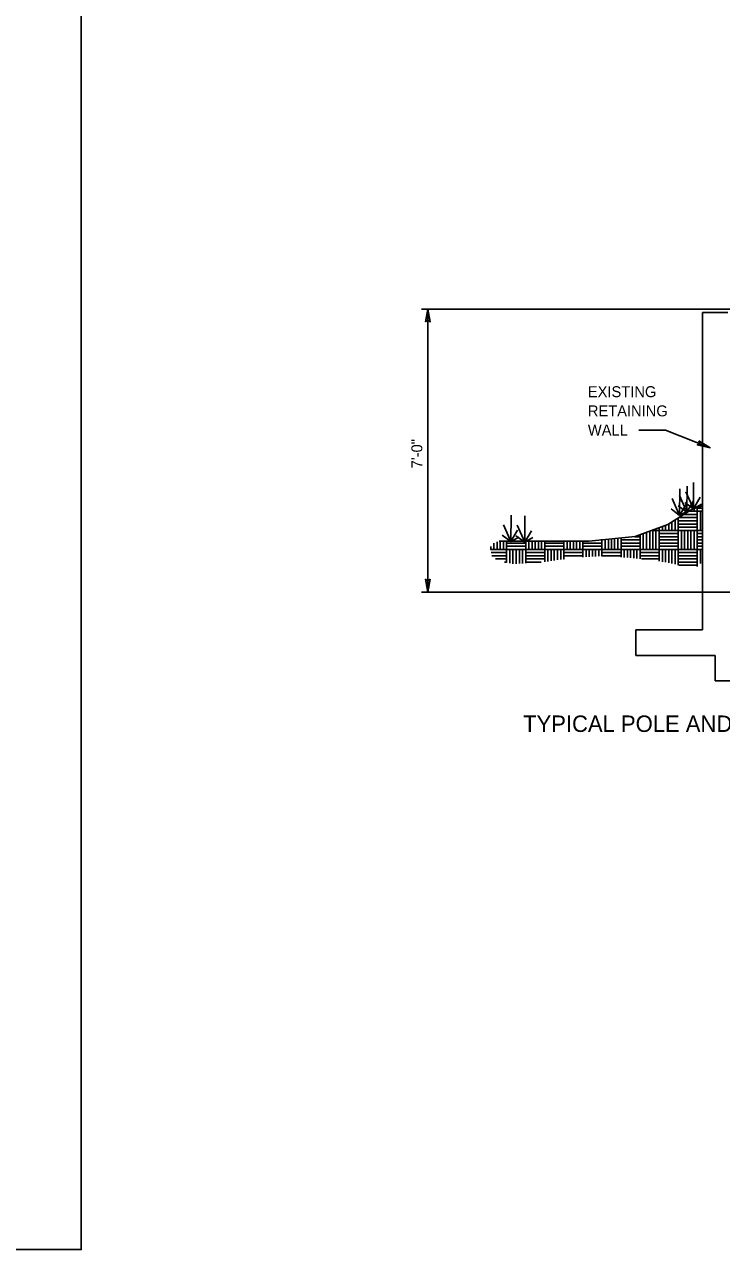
# Model space of a CAD drawing. Extents: x 99836 to 115004, y 99786 to 102182.
# Drawn here: x 113314 to 114076, y 99886 to 101226 of the extents above; entities that cross this region are included whole.
import ezdxf

# ---------------------------------------------------------------- set-up
doc = ezdxf.new("R2010")
doc.units = 0
doc.layers.add('Border Organizer Shape', color=7, linetype='Continuous')
doc.layers.add('Default', color=7, linetype='Continuous')

msp = doc.modelspace()

# ---------------------------------------------------------------- linework, layer by layer
at = {"layer": 'Border Organizer Shape'}
for p, q in [((114104.3, 100915.1), (113748, 100915.1)), ((113755.1, 100605.4), (113755.1, 100915.1)), ((114055.4, 100564), (114055.4, 100911.5)), ((114083.2, 100911.5), (114055.4, 100911.5)), ((113985.7, 100782.7), (114014.9, 100782.7)), ((114014.9, 100782.7), (114063.7, 100763.4)), ((114030.5, 100689.4), (114030.8, 100718.3)), ((114045.6, 100696.6), (114037.4, 100715)), ((114038.4, 100692.7), (114038.6, 100721.5)), ((114045.6, 100696.6), (114045.8, 100725.4)), ((114030.5, 100689.4), (114022.4, 100707.9)), ((114038.4, 100692.7), (114030.3, 100711.1)), ((114030.5, 100689.4), (114037.9, 100702)), ((114045.6, 100696.6), (114036.1, 100703.6)), ((114038.4, 100692.7), (114045.7, 100705.3)), ((114045.6, 100696.6), (114052.9, 100709.2)), ((114045.6, 100696.6), (114054.5, 100701.6)), ((113846, 100660.7), (113846.2, 100689.5)), ((113861, 100660.1), (113861.2, 100688.9)), ((114017.4, 100679.4), (114044, 100696)), ((114030.5, 100689.4), (114021.1, 100696.4)), ((114038.4, 100692.7), (114029, 100699.7)), ((114030.5, 100689.4), (114039.5, 100694.4)), ((114035, 100690.4), (114049.8, 100690.4)), ((114038.4, 100692.7), (114047.3, 100697.7)), ((114040.5, 100693.8), (114049.8, 100693.8)), ((114042.8, 100693.8), (114042.8, 100695.3)), ((114044, 100696), (114055.4, 100699.8)), ((114046.3, 100693.8), (114046.3, 100696.8)), ((114049.8, 100693.8), (114049.8, 100697.9)), ((114049.8, 100697.3), (114055.4, 100697.3)), ((114049.8, 100673), (114049.8, 100693.8)), ((114049.8, 100693.8), (114055.4, 100693.8)), ((114053.3, 100673), (114053.3, 100693.8)), ((113846, 100660.7), (113837.8, 100679.1)), ((113861, 100660.1), (113852.9, 100678.5)), ((113981.9, 100666.1), (114017.4, 100679.4)), ((114008.1, 100673), (114008.1, 100675.9)), ((114011.6, 100673), (114011.6, 100677.2)), ((114015, 100673), (114015, 100678.5)), ((114018.5, 100673), (114018.5, 100680.1)), ((114022, 100673), (114022, 100682.3)), ((114025.5, 100673), (114025.5, 100684.4)), ((114028.9, 100673), (114028.9, 100686.6)), ((114028.9, 100683.4), (114049.8, 100683.4)), ((114028.9, 100679.9), (114049.8, 100679.9)), ((114028.9, 100676.5), (114049.8, 100676.5)), ((114029.4, 100686.9), (114049.8, 100686.9)), ((113830.9, 100652.1), (113830.9, 100660.5)), ((113833, 100661.3), (113931, 100661.3)), ((113834.3, 100652.1), (113834.3, 100661.3)), ((113846, 100660.7), (113836.5, 100667.7)), ((113837.8, 100652.1), (113837.8, 100661.3)), ((113841.3, 100652.1), (113841.3, 100661.3)), ((113846, 100660.7), (113853.3, 100673.3)), ((113846, 100660.7), (113854.9, 100665.7)), ((113861, 100660.1), (113851.5, 100667)), ((113861, 100660.1), (113868.3, 100672.6)), ((113861, 100660.1), (113869.9, 100665)), ((113862.1, 100652.1), (113862.1, 100661.3)), ((113865.6, 100652.1), (113865.6, 100661.3)), ((113869.1, 100652.1), (113869.1, 100661.3)), ((113872.6, 100652.1), (113872.6, 100661.3)), ((113876, 100652.1), (113876, 100661.3)), ((113879.5, 100652.1), (113879.5, 100661.3)), ((113883, 100652.1), (113883, 100661.3)), ((113903.8, 100652.1), (113903.8, 100661.3)), ((113907.3, 100652.1), (113907.3, 100661.3)), ((113910.8, 100652.1), (113910.8, 100661.3)), ((113914.3, 100652.1), (113914.3, 100661.3)), ((113917.7, 100652.1), (113917.7, 100661.3)), ((113921.2, 100652.1), (113921.2, 100661.3)), ((113924.7, 100652.1), (113924.7, 100661.3)), ((113931, 100661.3), (113981.9, 100666.1)), ((113944.4, 100662.6), (113945.5, 100662.6)), ((113945.5, 100652.1), (113945.5, 100662.7)), ((113949, 100652.1), (113949, 100663)), ((113952.5, 100652.1), (113952.5, 100663.3)), ((113956, 100652.1), (113956, 100663.7)), ((113959.4, 100652.1), (113959.4, 100664)), ((113962.9, 100652.1), (113962.9, 100664.3)), ((113966.4, 100652.1), (113966.4, 100664.6)), ((113966.4, 100662.6), (113987.2, 100662.6)), ((113981.6, 100666), (113987.2, 100666)), ((113987.2, 100652.1), (113987.2, 100668.1)), ((113990.7, 100652.1), (113990.7, 100669.4)), ((113994.2, 100652.1), (113994.2, 100670.7)), ((113997.7, 100652.1), (113997.7, 100672)), ((114000.4, 100673), (114008.1, 100673)), ((114001.1, 100652.1), (114001.1, 100673)), ((114004.6, 100652.1), (114004.6, 100673)), ((114008.1, 100652.1), (114008.1, 100673)), ((114008.1, 100673), (114028.9, 100673)), ((114008.1, 100669.5), (114028.9, 100669.5)), ((114008.1, 100666), (114028.9, 100666)), ((114008.1, 100662.6), (114028.9, 100662.6)), ((114028.9, 100652.1), (114028.9, 100673)), ((114028.9, 100673), (114049.8, 100673)), ((114032.4, 100652.1), (114032.4, 100673)), ((114035.9, 100652.1), (114035.9, 100673)), ((114039.4, 100652.1), (114039.4, 100673)), ((114042.8, 100652.1), (114042.8, 100673)), ((114046.3, 100652.1), (114046.3, 100673)), ((114049.8, 100652.1), (114049.8, 100673)), ((114049.8, 100673), (114055.5, 100673)), ((114049.8, 100669.5), (114055.5, 100669.5)), ((114049.8, 100666), (114055.5, 100666)), ((114049.8, 100662.6), (114055.5, 100662.6)), ((113823.8, 100652.1), (113841.3, 100652.1)), ((113823.9, 100652.1), (113823.9, 100655.3)), ((113824.4, 100648.7), (113841.3, 100648.7)), ((113827.4, 100652.1), (113827.4, 100659.1)), ((113841.3, 100659.1), (113862.1, 100659.1)), ((113841.3, 100655.6), (113862.1, 100655.6)), ((113841.3, 100637.8), (113841.3, 100652.1)), ((113841.3, 100652.1), (113862.1, 100652.1)), ((113844.8, 100637), (113844.8, 100652.1)), ((113848.2, 100636.2), (113848.2, 100652.1)), ((113851.7, 100636.4), (113851.7, 100652.1)), ((113855.2, 100636.6), (113855.2, 100652.1)), ((113858.7, 100636.8), (113858.7, 100652.1)), ((113862.1, 100637.1), (113862.1, 100652.1)), ((113862.1, 100652.1), (113883, 100652.1)), ((113862.1, 100648.7), (113883, 100648.7)), ((113883, 100659.1), (113903.8, 100659.1)), ((113883, 100655.6), (113903.8, 100655.6)), ((113883, 100638.5), (113883, 100652.1)), ((113883, 100652.1), (113903.8, 100652.1)), ((113886.5, 100638.9), (113886.5, 100652.1)), ((113889.9, 100639.5), (113889.9, 100652.1)), ((113893.4, 100640), (113893.4, 100652.1)), ((113896.9, 100640.6), (113896.9, 100652.1)), ((113900.4, 100641.1), (113900.4, 100652.1)), ((113903.8, 100641.6), (113903.8, 100652.1)), ((113903.8, 100652.1), (113924.7, 100652.1)), ((113903.8, 100648.7), (113924.7, 100648.7)), ((113924.7, 100659.1), (113945.5, 100659.1)), ((113924.7, 100655.6), (113945.5, 100655.6)), ((113924.7, 100643.7), (113924.7, 100652.1)), ((113924.7, 100652.1), (113945.5, 100652.1)), ((113928.2, 100643.9), (113928.2, 100652.1)), ((113931.6, 100644.1), (113931.6, 100652.1)), ((113935.1, 100644.3), (113935.1, 100652.1)), ((113938.6, 100644.4), (113938.6, 100652.1)), ((113942.1, 100644.6), (113942.1, 100652.1)), ((113945.5, 100644.8), (113945.5, 100652.1)), ((113945.5, 100652.1), (113966.4, 100652.1)), ((113945.5, 100648.7), (113966.4, 100648.7)), ((113966.4, 100659.1), (113987.2, 100659.1)), ((113966.4, 100655.6), (113987.2, 100655.6)), ((113966.4, 100643.6), (113966.4, 100652.1)), ((113966.4, 100652.1), (113987.2, 100652.1)), ((113969.9, 100643.4), (113969.9, 100652.1)), ((113973.3, 100643.1), (113973.3, 100652.1)), ((113976.8, 100642.9), (113976.8, 100652.1)), ((113980.3, 100642.6), (113980.3, 100652.1)), ((113983.8, 100642.2), (113983.8, 100652.1)), ((113987.2, 100641.9), (113987.2, 100652.1)), ((113987.2, 100652.1), (114008.1, 100652.1)), ((113987.2, 100648.7), (114008.1, 100648.7)), ((114008.1, 100659.1), (114028.9, 100659.1)), ((114008.1, 100655.6), (114028.9, 100655.6)), ((114008.1, 100639.1), (114008.1, 100652.1)), ((114008.1, 100652.1), (114028.9, 100652.1)), ((114011.6, 100638.6), (114011.6, 100652.1)), ((114015, 100638), (114015, 100652.1)), ((114018.5, 100637.5), (114018.5, 100652.1)), ((114022, 100636.8), (114022, 100652.1)), ((114025.5, 100635.9), (114025.5, 100652.1)), ((114028.9, 100634.9), (114028.9, 100652.1)), ((114028.9, 100652.1), (114049.8, 100652.1)), ((114028.9, 100648.7), (114049.8, 100648.7)), ((114049.8, 100659.1), (114055.5, 100659.1)), ((114049.8, 100655.6), (114055.6, 100655.6)), ((114049.8, 100633.4), (114049.8, 100652.1)), ((114049.8, 100652.1), (114055.6, 100652.1)), ((114053.3, 100636.6), (114053.3, 100652.1)), ((113825, 100645.2), (113841.3, 100645.2)), ((113829, 100641.7), (113841.3, 100641.7)), ((113839, 100638.2), (113841.3, 100638.2)), ((113862.1, 100645.2), (113883, 100645.2)), ((113862.1, 100641.7), (113883, 100641.7)), ((113862.1, 100638.2), (113879.2, 100638.2)), ((113903.8, 100645.2), (113924.7, 100645.2)), ((113903.8, 100641.7), (113904.3, 100641.7)), ((113945.5, 100645.2), (113966.4, 100645.2)), ((113987.2, 100645.2), (114008.1, 100645.2)), ((113988.8, 100641.7), (114008.1, 100641.7)), ((114028.9, 100645.2), (114049.8, 100645.2)), ((114028.9, 100641.7), (114049.8, 100641.7)), ((114028.9, 100638.2), (114049.8, 100638.2)), ((114029.5, 100634.8), (114049.8, 100634.8)), ((114147, 100605.4), (113748, 100605.4)), ((113982.4, 100536.2), (113982.4, 100564)), ((113982.4, 100564), (114055.4, 100564)), ((113982.4, 100536.2), (114069.3, 100536.2)), ((114069.3, 100508.4), (114069.3, 100536.2)), ((114069.3, 100508.4), (114097.1, 100508.4))]:
    msp.add_line(p, q, dxfattribs=at)
for points in [[(113752.7, 100901), (113755.1, 100915.1), (113757.5, 100901), (113755.1, 100903.2)], [(114051.4, 100770.8), (114063.7, 100763.4), (114049.7, 100766.4), (114052.6, 100767.8)], [(113757.5, 100619.5), (113755.1, 100605.4), (113752.7, 100619.5), (113755.1, 100617.3)]]:
    msp.add_lwpolyline(points, close=True, dxfattribs=at)
at = {"layer": 'Default'}
msp.add_lwpolyline([(110176.3, 102085.7), (113376, 102085.7), (113376, 99886.1), (110176.3, 99886.1)], close=True, dxfattribs=at)

# ---------------------------------------------------------------- texts
at = {"layer": 'Border Organizer Shape'}
for s, height, p in [('EXISTING ', 12, (113930.1, 100818.7)), ('RETAINING ', 12, (113930.1, 100797.7)), ('WALL ', 12, (113930.1, 100776.7)), ('TYPICAL POLE AND POWER FOUNDATION DETAIL BEHIND NOISE WALL', 18, (113859.3, 100452.4))]:
    msp.add_text(s, height=height, dxfattribs=at).set_placement(p)
msp.add_text('7\'-0"', height=12, rotation=90, dxfattribs=at).set_placement((113749.1, 100740.9))

doc.saveas('drawing.dxf')
